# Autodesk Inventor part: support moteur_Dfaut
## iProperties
Created: 2007-07
Part Number: support moteur_Dfaut
Document SubType Name: Modeling
Designer: EF
Density: 1 g/cm^3
Author: EF
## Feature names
1. Base1
